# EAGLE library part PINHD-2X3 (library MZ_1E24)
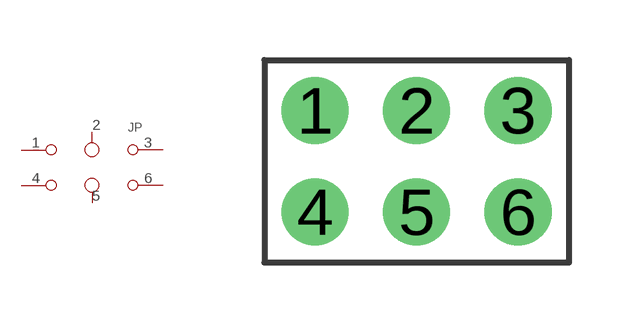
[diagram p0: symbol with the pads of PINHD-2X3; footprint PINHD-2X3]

Designator prefix JP

## PINHD-2X3  [PINHD-2X3]
1  1  pas
2  2  pas
3  3  pas
4  4  pas
5  5  pas
6  6  pas

## Footprint PINHD-2X3 (pad centres in mm)
drill 1.016 pad 1.676 round: 1 -2.54,1.27; 2 0,1.27; 3 2.54,1.27; 4 -2.54,-1.27; 5 0,-1.27; 6 2.54,-1.27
